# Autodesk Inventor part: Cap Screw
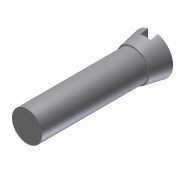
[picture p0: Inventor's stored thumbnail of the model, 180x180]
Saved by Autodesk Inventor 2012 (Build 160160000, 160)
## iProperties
Shininess: 77.0
Length Units: 11269
Angle Units: 11279
Time Units: 11290
Mass Units: 11283
Length Display Precision: 3
Angle Display Precision: 2
Created: 2002-02
Part Number: Cap Screw
Document SubType Name: Modeling
Designer: ***
Density: 1 g/cm^3
Material: Default
Density: 0.0
Volumn: 0.0
Area: 0.0
PropertySet Name: Model Information
Control State: 0
Master: False
Checked Out: False
Author: ***
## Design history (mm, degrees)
sketch "Sketch1"
  geometry: L1 (0, 27.83)-(4, 27.83); L2 (4, 27.83)-(3.25, 23.83); L3 (3.25, 23.83)-(0, 23.83); L4 (0, 23.83)-(0, 27.83)
  constraints: 8 end point, 1 horizontal, 1 parallel, 1 perpendicular, 1 point on line
  dimensions: "d2" = 4 distance from line of L1 L2.end; "d5" = 8 diameter of L1.end L4; "d6" = 6.5 diameter of L3.start L4; "d14" = 4 distance of L3.end L1.start
revolve "Revolution1" sketch "Sketch1" stored, may be unused: angle "d7" = 90 deg
sketch "Sketch2"
  geometry: C1 r 3 at (0, 0)
  constraints: 1 centre point
  dimensions: "d8" = 6 diameter of C1
extrude "Extrusion1" join sketch "Sketch2" distance "d9" = 21; taper "d10" = 0 deg
sketch "Sketch3"
  geometry: L1 (-1, 28.967)-(1, 28.967); L2 (1, 28.967)-(1, 26.33); L3 (1, 26.33)-(-1, 26.33); L4 (-1, 26.33)-(-1, 28.967); L5 (-4, 27.83)-(4, 27.83) reference
  constraints: 8 end point, 2 parallel, 1 horizontal, 1 perpendicular
  dimensions: "d11" = 2 distance of L1.start L1.end; "d15" = 1.5 distance between parallel lines of L5 L3
extrude "Extrusion2" cut sketch "Sketch3" stored distance "d12" = 24; taper "d13" = 0 deg
body "Solid1"
